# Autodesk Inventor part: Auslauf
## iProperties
Created: 2010-08
Part Number: Auslauf
Document SubType Name: Modeling
Designer: Boekels
Density: 1 g/cm^3
Author: Boekels
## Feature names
1. Extrusion1
2. Extrusion2
3. Trennen1
4. Trennen2
